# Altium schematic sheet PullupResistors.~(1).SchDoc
size A4
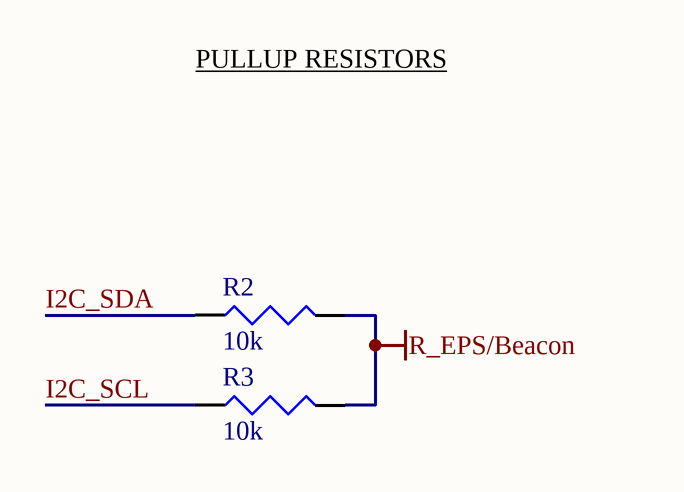
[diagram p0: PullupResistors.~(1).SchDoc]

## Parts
R2  value 10k  [J1-0603]  (hidden comment: Res3)
R3  value 10k  [J1-0603]  (hidden comment: Res3)

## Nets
R_EPS/Beacon: R2.2 R3.2
I2C_SCL: R3.1
I2C_SDA: R2.1

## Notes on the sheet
- PULLUP RESISTORS

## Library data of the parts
R2 R3 = Res3: Resistor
